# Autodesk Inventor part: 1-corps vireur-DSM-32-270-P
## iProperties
Created: 2011-02
Part Number: 1-corps vireur-DSM-32-270-P
Document SubType Name: Modeling
Designer: eric
Density: 1 g/cm^3
Author: eric
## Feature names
1. Base1
